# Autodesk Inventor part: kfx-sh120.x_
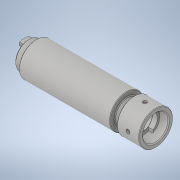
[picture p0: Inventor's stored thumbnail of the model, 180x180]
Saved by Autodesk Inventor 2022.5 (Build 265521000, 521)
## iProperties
Created: 2021-10
Part Number: kfx-sh120.x_
Material: 一般
Document SubType Name: Modeling
Designer: ImaoCorp
Density: 1 g/cm^3
Appearance: 既定
Sending System: SOLIDWORKS 2019-2019304
MC: AMD64
MC_MODEL: Intel64 Family 6 Model 60 Stepping 3, GenuineIntel
OS: Windows_NT
FRU: Parasolid Version 31.0, build 290,  9- 1-2019
FORMAT: text
GUISE: transmit
KEY: kfx-sh120
FILE: kfx-sh120.x_t
DATE: Thu Oct 14 10:00:14 2021
Author: ImaoCorp
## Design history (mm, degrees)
feature "Base1"
node "ソリッド1"
